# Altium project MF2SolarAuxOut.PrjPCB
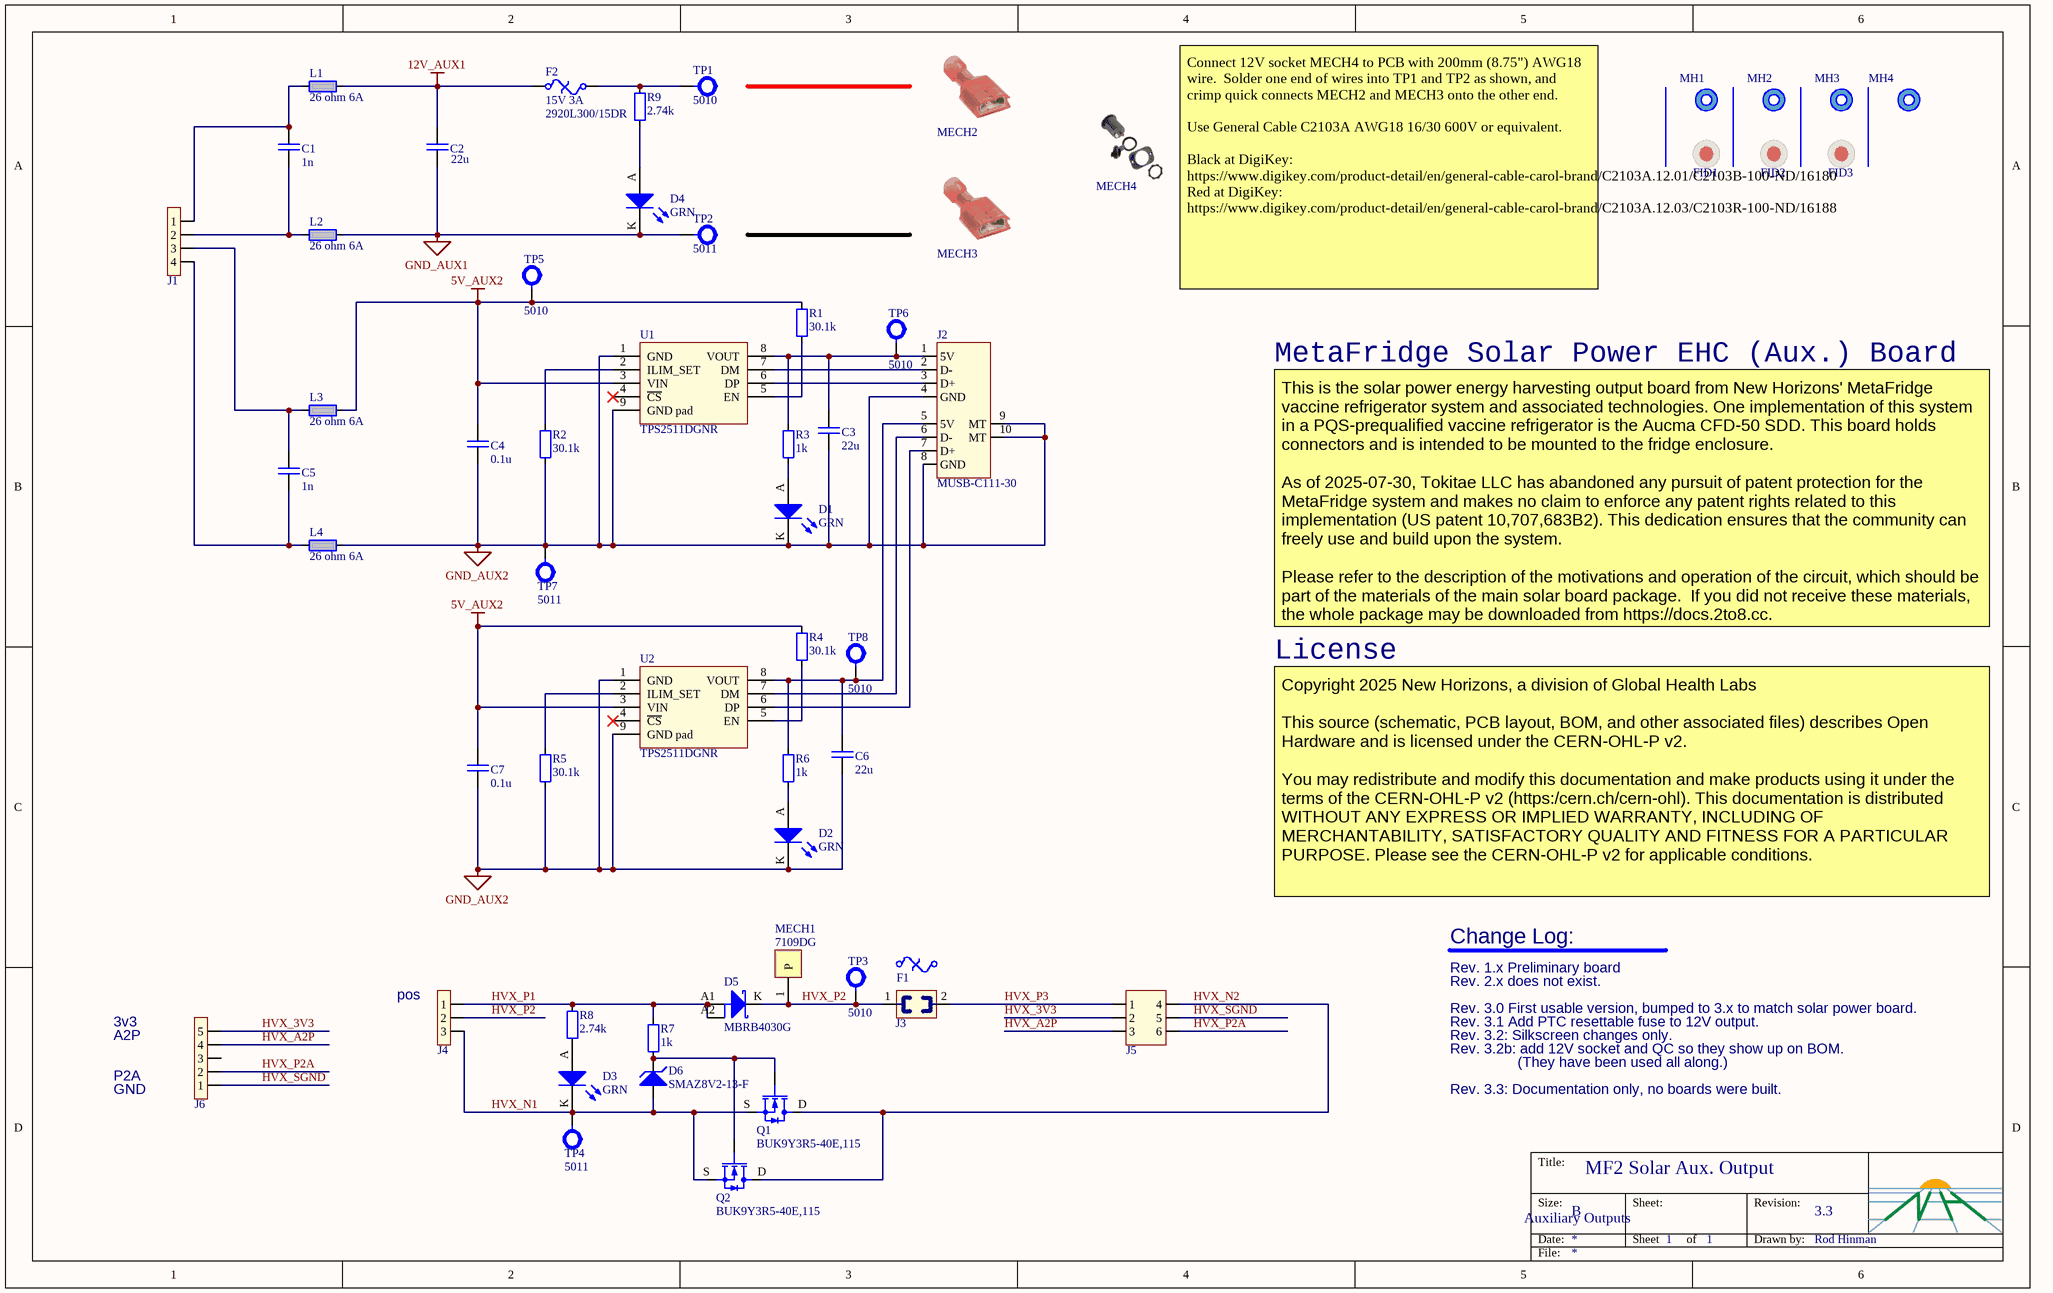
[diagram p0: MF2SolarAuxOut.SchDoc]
nhToday: 2019-01-10; nhSheetTotal: 1; nhRev: 3.3; nhProjName: MF2 Solar Aux. Output; nhEngPhone: 808-989-0977; nhEngName: Rod Hinman; nhEngEmail: rod@auroraresearch.com
1 sheet, 57 parts. Net scope: global (net labels, ports and power ports of the same name join across sheets).
Board file: MF2SolarAuxOut.PcbDoc

## Sheet MF2SolarAuxOut.SchDoc
size B; SheetNumber: 1; nhSheetName: Auxiliary Outputs

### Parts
C1  value_text: 1n  [CAPC1608X09N[0603]]  (hidden comment: 50V C0G 0603)
C2  value_text: 22u  [CAPC2012X145]  (hidden comment: 16V X5R 0805)
C3  value_text: 22u  [CAPC2012X145]  (hidden comment: 16V X5R 0805)
C4  value_text: 0.1u  [CAPC1608X09N[0603]]  (hidden comment: 50V X7R 0603)
C5  value_text: 1n  [CAPC1608X09N[0603]]  (hidden comment: 50V C0G 0603)
C6  value_text: 22u  [CAPC2012X145]  (hidden comment: 16V X5R 0805)
C7  value_text: 0.1u  [CAPC1608X09N[0603]]  (hidden comment: 50V X7R 0603)
D1  GRN  [LED-5MM-GREEN]
D2  GRN  [LED-5MM-GREEN]
D3  GRN  [LED-5MM-GREEN]
D4  GRN  [LED-5MM-GREEN]
D5  manufacturer_pn: MBRB4030G  [D2PAK_2_ANODE_NOSILK]  (hidden comment: 30V 40A)
D6  manufacturer_pn: SMAZ8V2-13-F  [DO-214AC]  (hidden comment: 8.2V 1W)
F1  58VDC 20A  [FUSE_MINI_ATO_20A]  (value not drawn)  (mechanical)
F2  15V 3A  manufacturer_pn: 2920L300/15DR  [FUSC7351X12N[2920]]
FID1  fiducial  [FIDUCIAL_1_3]  (value not drawn)  (no BOM)
FID2  fiducial  [FIDUCIAL_1_3]  (value not drawn)  (no BOM)
FID3  fiducial  [FIDUCIAL_1_3]  (value not drawn)  (no BOM)
J1  1x4 3.96mm  [AMP_1-1123723-4]  (value not drawn)
J2  manufacturer_pn: MUSB-C111-30  [AMPH_MUSB-C111-00]  (hidden comment: USB A)
J3  MINI  [KEYSTONE_3568]  (value not drawn)
J4  JST VL  [JST_B03P-VL]  (value not drawn)
J5  MX150L  [MOLEX_0194270018]  (value not drawn)
J6  1x5 2.5mm  [JST_B5B-XH-A(LF)(SN)]  (value not drawn)
L1  26 ohm 6A  [FER1608X100[0603]]
L2  26 ohm 6A  [FER1608X100[0603]]
L3  26 ohm 6A  [FER1608X100[0603]]
L4  26 ohm 6A  [FER1608X100[0603]]
MECH1  manufacturer_pn: 7109DG  [AAVID_7109DG]  (hidden comment: SMT)
MECH2  QC Female  [QUICK_CONNECT_6.35]  (value not drawn)  (mechanical)
MECH3  QC Female  [QUICK_CONNECT_6.35]  (value not drawn)  (mechanical)
MECH4  12V Socket  (value not drawn)  (mechanical)
MH1  mounting hole  [MOUNT_HOLE_4MM_NOCOPPER]  (value not drawn)  (no BOM)
MH2  mounting hole  [MOUNT_HOLE_4MM_NOCOPPER]  (value not drawn)  (no BOM)
MH3  mounting hole  [MOUNT_HOLE_4MM_NOCOPPER]  (value not drawn)  (no BOM)
MH4  mounting hole  [MOUNT_HOLE_4MM_NOCOPPER]  (value not drawn)  (no BOM)
Q1  manufacturer_pn: BUK9Y3R5-40E,115  [SOT669_LFPAK56]  (hidden comment: N-CH 40V 100A)
Q2  manufacturer_pn: BUK9Y3R5-40E,115  [SOT669_LFPAK56]  (hidden comment: N-CH 40V 100A)
R1  value_text: 30.1k  [RESC1608X05AN[0603]]  (hidden comment: 1/10W 0603 1%)
R2  value_text: 30.1k  [RESC1608X05AN[0603]]  (hidden comment: 1/10W 0603 1%)
R3  value_text: 1k  [RESC1608X05AN[0603]]  (hidden comment: 1/10W 0603 1%)
R4  value_text: 30.1k  [RESC1608X05AN[0603]]  (hidden comment: 1/10W 0603 1%)
R5  value_text: 30.1k  [RESC1608X05AN[0603]]  (hidden comment: 1/10W 0603 1%)
R6  value_text: 1k  [RESC1608X05AN[0603]]  (hidden comment: 1/10W 0603 1%)
R7  value_text: 1k  [RESC1608X05AN[0603]]  (hidden comment: 1/10W 0603 1%)
R8  value_text: 2.74k  [RESC1608X05AN[0603]]  (hidden comment: 1/10W 0603 1%)
R9  value_text: 2.74k  [RESC1608X05AN[0603]]  (hidden comment: 1/10W 0603 1%)
TP1  manufacturer_pn: 5010  [KEYSTONE_5010]  (hidden comment: TP RED)
TP2  manufacturer_pn: 5011  [KEYSTONE_5011]  (hidden comment: TP BLK)
TP3  manufacturer_pn: 5010  [KEYSTONE_5010]  (hidden comment: TP RED)
TP4  manufacturer_pn: 5011  [KEYSTONE_5011]  (hidden comment: TP BLK)
TP5  manufacturer_pn: 5010  [KEYSTONE_5010]  (hidden comment: TP RED)
TP6  manufacturer_pn: 5010  [KEYSTONE_5010]  (hidden comment: TP RED)
TP7  manufacturer_pn: 5011  [KEYSTONE_5011]  (hidden comment: TP BLK)
TP8  manufacturer_pn: 5010  [KEYSTONE_5010]  (hidden comment: TP RED)
U1  manufacturer_pn: TPS2511DGNR  [TSOP65P490X110_HS-9N]  (hidden comment: TPS2511)
U2  manufacturer_pn: TPS2511DGNR  [TSOP65P490X110_HS-9N]  (hidden comment: TPS2511)

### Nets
5V_AUX2: C4.1 C7.1 L3.1 R1.1 R4.1 TP5.1 U1.3(VIN) U2.3(VIN)
12V_AUX1: C2.1 F2.1 L1.1
GND_AUX1: C2.2 D4.K L2.1 TP2.1
GND_AUX2: C3.2 C4.2 C6.2 C7.2 D1.K D2.K J2.4(GND) J2.8(GND) J2.9(MT) J2.10(MT) L4.1 R2.2 R5.2 TP7.1 U1.1(GND) U1.9(GND_pad) U2.1(GND) U2.9(GND_pad)
HVX_3V3: J5.2 J6.5
HVX_A2P: J5.3 J6.4
HVX_N1: D3.K D6.A J4.3 Q1.S Q2.S TP4.1
HVX_N2: J5.4 Q1.D Q2.D
HVX_P1: D5.A1 D5.A2 J4.1 R7.1 R8.1
HVX_P2: D5.K J3.1 J4.2 MECH1.1(P) TP3.1
HVX_P2A: J5.6 J6.2
HVX_P3: J3.2 J5.1
HVX_SGND: J5.5 J6.1
NetC1_1: C1.1 J1.1 L1.2
NetC1_2: C1.2 J1.2 L2.2
NetC3_1: C3.1 J2.1(5V) R3.1 TP6.1 U1.8(VOUT)
NetC5_1: C5.1 J1.3 L3.2
NetC5_2: C5.2 J1.4 L4.2
NetC6_1: C6.1 J2.5(5V) R6.1 TP8.1 U2.8(VOUT)
NetD1_A: D1.A R3.2
NetD2_A: D2.A R6.2
NetD3_A: D3.A R8.2
NetD4_A: D4.A R9.2
NetD6_K: D6.K Q1.G Q2.G R7.2
NetF2_2: F2.2 R9.1 TP1.1
NetJ2_2: J2.2(D-) U1.7(DM)
NetJ2_3: J2.3(D+) U1.6(DP)
NetJ2_6: J2.6(D-) U2.7(DM)
NetJ2_7: J2.7(D+) U2.6(DP)
NetR1_2: R1.2 U1.5(EN)
NetR2_1: R2.1 U1.2(ILIM_SET)
NetR4_2: R4.2 U2.5(EN)
NetR5_1: R5.1 U2.2(ILIM_SET)

Not connected (* = marked no-connect by the designer): J6 3; U1 4(~{CS})*; U2 4(~{CS})*

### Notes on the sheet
- (near MECH4) Connect 12V socket MECH4 to PCB with 200mm (8.75") AWG18 wire.  Solder one end of wires into TP1 and TP2 as shown, and crimp quick connects MECH2 and MECH3 onto the other end.
  Use General Cable C2103A AWG18 16/30 600V or equivalent.
  Black at DigiKey: https://www.digikey.com/product-detail/en/general-cable-carol-brand/C2103A.12.01/C2103B-100-ND/16180
  Red at DigiKey: https://www.digikey.com/product-detail/en/general-cable-carol-brand/C2103A.12.03/C2103R-100-ND/16188
- MetaFridge Solar Power EHC (Aux.) Board
- This is the solar power energy harvesting output board from New Horizons' MetaFridge vaccine refrigerator system and associated technologies. One implementation of this system in a PQS-prequalified vaccine refrigerator is the Aucma CFD-50 SDD. This board holds connectors and is intended to be mounted to the fridge enclosure.
  As of 2025-07-30, Tokitae LLC has abandoned any pursuit of patent protection for the MetaFridge system and makes no claim to enforce any patent rights related to this implementation (US patent 10,707,683B2). This dedication ensures that the community can freely use and build upon the system.
  Please refer to the description of the motivations and operation of the circuit, which should be part of the materials of the main solar board package.  If you did not receive these materials, the whole package may be downloaded from https://docs.2to8.cc.
- License
- Copyright 2025 New Horizons, a division of Global Health Labs
  This source (schematic, PCB layout, BOM, and other associated files) describes Open Hardware and is licensed under the CERN-OHL-P v2.
  You may redistribute and modify this documentation and make products using it under the terms of the CERN-OHL-P v2 (https:/cern.ch/cern-ohl). This documentation is distributed WITHOUT ANY EXPRESS OR IMPLIED WARRANTY, INCLUDING OF MERCHANTABILITY, SATISFACTORY QUALITY AND FITNESS FOR A PARTICULAR PURPOSE. Please see the CERN-OHL-P v2 for applicable conditions.
- Change Log:
- Rev. 1.x Preliminary board
- 3v3
- A2P
- (near J4) pos
- Rev. 3.2: Silkscreen changes only.
- Rev. 3.1 Add PTC resettable fuse to 12V output.
- Rev. 3.0 First usable version, bumped to 3.x to match solar power board.
- Rev. 2.x does not exist.
- P2A
- GND
- Rev. 3.2b: add 12V socket and QC so they show up on BOM.
- Rev. 3.3: Documentation only, no boards were built.
- (They have been used all along.)

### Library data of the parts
C1 C5 = CAP-00053: 1000pF ±5% 50V Ceramic Capacitor C0G, NP0 0603 (1608 Metric); manufacturer: Murata Electronics North America; manufacturer_pn: GRM1885C1H102JA01D; id: 147791; value: 1E-9; Key Parameters: V >= 16V
C2 C3 C6 = CAP-00031: 22µF 16V Ceramic Capacitor X5R 0805 (2012 Metric) 0.079" L x 0.049" W (2.00mm x 1.25mm); manufacturer: Murata Electronics North America; manufacturer_pn: GRM21BR61C226ME44L; id: 137130; value: 2.2E-5; Key Parameters: V >= 16V
C4 C7 = CAP-00001: 0.10µF 50V Ceramic Capacitor X7R 0603 (1608 Metric) 0.063" L x 0.031" W (1.60mm x 0.80mm); manufacturer: Murata Electronics North America; manufacturer_pn: GCM188R71H104KA57J; id: 136482; value: 1E-7; Key Parameters: v >= 6.3V
D1-D4 = LED-00019: LED Panel Indicator Green Diffused 60° 2.2V 25mA Round with Domed Top, 3mm (T-1) Wire Leads - 6in (152.40mm); manufacturer_pn: SSI-RM3091SUGD-150; manufacturer: Lumex Opto/Components Inc.; id: 189302
D5 = DIO-00034: Diode Schottky 30V 40A Surface Mount D2PAK; manufacturer: ON Semiconductor; id: 188970
D6 = DIO-00017: Zener Diode 8.2V 1W ±5% Surface Mount SMA; manufacturer: Diodes Incorporated; id: 141314
F1 = FUSE-00009: FUSE AUTO 20A 58VDC BLADE MINI; manufacturer_pn: 0997020.WXN; manufacturer: Littelfuse Inc.; id: 169759
F2 = FUSE-00010: Polymeric PTC Resettable Fuse 15V 3A Ih Surface Mount 2920 (7351 Metric), Concave; manufacturer: Littelfuse Inc.; id: 199285
FID1-FID3 = NOBOM-00010: Fiducial, 1mm dia, 3mm solder mask opening; manufacturer: New Horizons; id: 138118
J1 = CONN-00068: 4 Positions Header, Unshrouded Connector 0.156" (3.96mm) Through Hole Tin (GRN); manufacturer_pn: 6-1123723-4; manufacturer: TE Connectivity AMP Connectors; id: 140461
J2 = CONN-00127: USB - A, Stacked USB 2.0 Receptacle Connector 8 Position Panel Mount, Through Hole, Right Angle; manufacturer: Amphenol Commercial Products; id: 188959
J3 = CONN-00117: FUSE HOLDER BLADE 500V 20A PCB; manufacturer_pn: 3568; manufacturer: Keystone Electronics; id: 169758
J4 = CONN-00119: 3 Positions Header Connector 0.244" (6.20mm) Through Hole Tin; manufacturer: JST Sales America Inc.; manufacturer_pn: B03P-VL; id: 170440
J5 = CONN-00128: 6 Positions Header Connector 0.230in (5.84mm) Panel Mount, Through Hole, Right Angle Tin; manufacturer_pn: 19427-0018; manufacturer: Molex, LLC; id: 188963
J6 = CONN-00116: 5 Positions Header Connector 0.098" (2.50mm) Through Hole Tin; manufacturer_pn: B5B-XH-A(LF)(SN); manufacturer: JST Sales America Inc.; id: 166570
L1-L4 = FER-00008: FERRITE BEAD 26 OHM 0603 1LN 7 mohm; manufacturer_pn: MPZ1608S260ATAH0; manufacturer: TDK Corporation; value_text: 26; id: 159931; value: 26
MECH1 = MECH-00028: Heat Sink TO-263 (D²Pak) Copper 2W @ 30°C Top Mount; manufacturer: Aavid Thermalloy; id: 188969
MECH2 MECH3 = MECH-00036: 0.250" (6.35mm) Quick Connect Female 18-22 AWG Crimp Connector Fully Insulated; manufacturer_pn: 2-520184-2; manufacturer: TE Connectivity AMP Connectors; id: 297892
MECH4 = MECH-00037: Auto Power Socket Cigarette Lighter Assembly 12V 20A Lockable, Nylon, Vibration and Weather Resistant Black; manufacturer_pn: AS212C; manufacturer: Memory Protection Devices; id: 297893
MH1-MH4 = NOBOM-00014: Mounting hole, 4mm NPT; manufacturer: New Horizons; id: 140641
Q1 Q2 = FET-00015: N-Channel 40V 100A (Tc) 167W (Tc) Surface Mount LFPAK56, Power-SO8; manufacturer: Nexperia USA Inc.; id: 189028
R1 R2 R4 R5 = RES-00026: RES SMD 30.1K OHM 1% 1/10W 0603; manufacturer_pn: ERJ-3EKF3012V; manufacturer: Panasonic Electronic Components; id: 137104; value: 30100; Key Parameters: 1% required
R3 R6 R7 = RES-00113: 1 kOhms ±1% 0.1W, 1/10W Chip Resistor 0603 (1608 Metric) Automotive AEC-Q200 Thick Film; manufacturer_pn: ERJ-3EKF1001V; manufacturer: Panasonic Electronic Components; id: 185365; value: 1000; Key Parameters: 5% OK
R8 R9 = RES-00055: RES SMD 2.74K OHM 1% 1/10W 0603; manufacturer_pn: ERJ-3EKF2741V; manufacturer: Panasonic Electronic Components; id: 144315; value: 2740; Key Parameters: 5% OK
TP1 TP3 TP5 TP6 TP8 = CONN-00027: TEST POINT PC MULTI PURPOSE RED; manufacturer: Keystone Electronics; id: 137440
TP2 TP4 TP7 = CONN-00028: TEST POINT PC MULTI PURPOSE BLK; manufacturer: Keystone Electronics; id: 137441
U1 U2 = ICPWR-00029: USB Dedicated Charging Port (DCP), Power Switch PMIC 8-MSOP-PowerPad; manufacturer: Texas Instruments; id: 171408

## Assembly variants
As Built: not fitted D2 Q2 TP1 TP2 TP3 TP4 TP5 TP6 TP7 TP8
